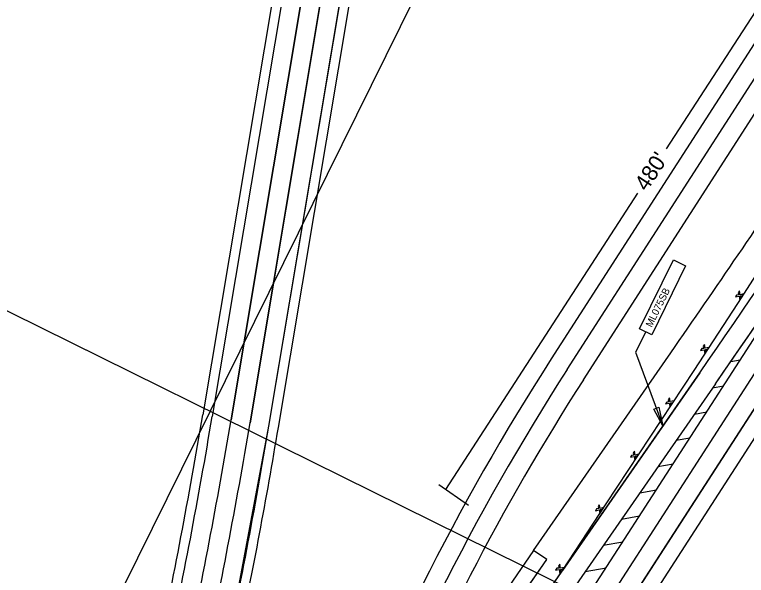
# Model space of a CAD drawing. Extents: x 14097936 to 14128734, y 8632000 to 8683104.
# Drawn here: x 14118895.5 to 14119353.7, y 8669041.8 to 8669393 of the extents above; entities that cross this region are included whole.
import ezdxf

# ---------------------------------------------------------------- set-up
doc = ezdxf.new("R2010")
doc.units = 0
for name, color, linetype in [('Cell', 7, 'Continuous'), ('dsn_stg_shd_prev', 7, 'Continuous'), ('dsnNonPlotable', 7, 'Continuous'), ('dsnPaintExistingChannelizingLaneWhite', 7, 'Continuous'), ('dsnPaintExistingDoubleCenterYellow', 7, 'Continuous'), ('dsnPaintExistingEdgeLineRightWhite', 7, 'Continuous'), ('dsnPaintExistingNoPassingYellow', 7, 'Continuous'), ('dsnPaintPlaceBrokenLaneWhite', 7, 'Continuous'), ('dsnPaintPlaceChannelizingLaneWhite', 7, 'Continuous'), ('dsnPaintPlaceChannelizingLaneYellow', 7, 'Continuous'), ('dsnPaintPlaceEdgeLineRightWhite', 7, 'Continuous'), ('dsnPavementRmvl', 7, 'Continuous'), ('dsnShadingPaved', 7, 'Continuous'), ('dsnStdLabel', 7, 'Continuous'), ('dsnStgShadingPropPav', 7, 'Continuous'), ('dsnTapePlaceChannelizingLaneWhite', 7, 'Continuous'), ('Text', 7, 'Continuous')]:
    doc.layers.add(name, color=color, linetype=linetype)

msp = doc.modelspace()

# ---------------------------------------------------------------- linework, layer by layer
at = {"layer": 'Cell'}
for p, q in [((14119347.58, 8669217.34), (14119346.82, 8669216.19)), ((14119349, 8669217.45), (14119347.58, 8669217.34)), ((14119349.29, 8669219.95), (14119348.54, 8669218.8)), ((14119348.54, 8669218.8), (14119349, 8669217.45)), ((14119349.78, 8669217.61), (14119349.29, 8669219.95)), ((14119352.12, 8669218.1), (14119349.78, 8669217.61)), ((14119349.94, 8669216.84), (14119351.36, 8669216.95)), ((14119350.4, 8669215.49), (14119349.94, 8669216.84)), ((14119351.36, 8669216.95), (14119352.12, 8669218.1)), ((14119346.82, 8669216.19), (14119349.16, 8669216.67)), ((14119349.16, 8669216.67), (14119349.64, 8669214.34)), ((14119349.64, 8669214.34), (14119350.4, 8669215.49)), ((14119327.42, 8669186.46), (14119326.66, 8669185.31)), ((14119326.66, 8669185.31), (14119327.12, 8669183.96)), ((14119327.9, 8669184.12), (14119327.42, 8669186.46)), ((14119325.7, 8669183.85), (14119324.95, 8669182.7)), ((14119324.95, 8669182.7), (14119327.29, 8669183.18)), ((14119327.12, 8669183.96), (14119325.7, 8669183.85)), ((14119327.29, 8669183.18), (14119327.77, 8669180.84)), ((14119327.77, 8669180.84), (14119328.52, 8669181.99)), ((14119330.24, 8669184.6), (14119327.9, 8669184.12)), ((14119328.06, 8669183.34), (14119329.49, 8669183.46)), ((14119328.52, 8669181.99), (14119328.06, 8669183.34)), ((14119329.49, 8669183.46), (14119330.24, 8669184.6)), ((14119305.52, 8669152.98), (14119304.77, 8669151.83)), ((14119306.01, 8669150.64), (14119305.52, 8669152.98)), ((14119303.81, 8669150.37), (14119303.05, 8669149.22)), ((14119303.05, 8669149.22), (14119305.39, 8669149.7)), ((14119305.23, 8669150.48), (14119303.81, 8669150.37)), ((14119304.77, 8669151.83), (14119305.23, 8669150.48)), ((14119305.39, 8669149.7), (14119305.87, 8669147.37)), ((14119305.87, 8669147.37), (14119306.63, 8669148.51)), ((14119308.34, 8669151.13), (14119306.01, 8669150.64)), ((14119306.17, 8669149.86), (14119307.59, 8669149.98)), ((14119306.63, 8669148.51), (14119306.17, 8669149.86)), ((14119307.59, 8669149.98), (14119308.34, 8669151.13)), ((14119281.83, 8669116.95), (14119281.07, 8669115.8)), ((14119281.07, 8669115.8), (14119283.41, 8669116.28)), ((14119283.25, 8669117.06), (14119281.83, 8669116.95)), ((14119283.54, 8669119.56), (14119282.79, 8669118.41)), ((14119282.79, 8669118.41), (14119283.25, 8669117.06)), ((14119283.41, 8669116.28), (14119283.89, 8669113.94)), ((14119284.03, 8669117.22), (14119283.54, 8669119.56)), ((14119286.36, 8669117.7), (14119284.03, 8669117.22)), ((14119284.19, 8669116.44), (14119285.61, 8669116.55)), ((14119284.65, 8669115.09), (14119284.19, 8669116.44)), ((14119285.61, 8669116.55), (14119286.36, 8669117.7)), ((14119283.89, 8669113.94), (14119284.65, 8669115.09)), ((14119261.58, 8669086.12), (14119260.82, 8669084.98)), ((14119260.82, 8669084.98), (14119261.28, 8669083.63)), ((14119262.06, 8669083.79), (14119261.58, 8669086.12)), ((14119264.4, 8669084.27), (14119262.06, 8669083.79)), ((14119263.64, 8669083.12), (14119264.4, 8669084.27)), ((14119259.86, 8669083.51), (14119259.11, 8669082.36)), ((14119259.11, 8669082.36), (14119261.44, 8669082.85)), ((14119261.28, 8669083.63), (14119259.86, 8669083.51)), ((14119261.44, 8669082.85), (14119261.93, 8669080.51)), ((14119261.93, 8669080.51), (14119262.68, 8669081.66)), ((14119262.22, 8669083.01), (14119263.64, 8669083.12)), ((14119262.68, 8669081.66), (14119262.22, 8669083.01)), ((14119236.9, 8669048.78), (14119236.06, 8669047.68)), ((14119236.06, 8669047.68), (14119236.43, 8669046.31)), ((14119237.21, 8669046.41), (14119236.9, 8669048.78)), ((14119235, 8669046.29), (14119234.17, 8669045.2)), ((14119234.17, 8669045.2), (14119236.53, 8669045.52)), ((14119236.43, 8669046.31), (14119235, 8669046.29)), ((14119236.53, 8669045.52), (14119236.85, 8669043.15)), ((14119236.85, 8669043.15), (14119237.69, 8669044.25)), ((14119239.58, 8669046.73), (14119237.21, 8669046.41)), ((14119237.32, 8669045.62), (14119238.75, 8669045.64)), ((14119237.69, 8669044.25), (14119237.32, 8669045.62)), ((14119238.75, 8669045.64), (14119239.58, 8669046.73))]:
    msp.add_line(p, q, dxfattribs=at)
at = {"layer": 'dsn_stg_shd_prev'}
for p, q in [((14119060.64, 8669134.39), (14119230.09, 8670146.06)), ((14119151.79, 8669969.11), (14119013.3, 8669142.32))]:
    msp.add_line(p, q, dxfattribs=at)
for radius, start in [(3476, 347.93292), (3524, 348.29238)]:
    msp.add_arc((14115585.06, 8669716.53), radius, start, 350.49147, dxfattribs=at)
at = {"layer": 'dsnNonPlotable'}
for points in [[(14119315.27, 8668607.09), (14120010, 8670012.23), (14119557.31, 8670236.05), (14118862.58, 8668830.91)], [(14118047.21, 8667875.87), (14118741.94, 8669281.01), (14119647.32, 8668833.36), (14118952.59, 8667428.23)]]:
    msp.add_lwpolyline(points, close=True, dxfattribs=at)
at = {"layer": 'dsnPaintExistingChannelizingLaneWhite'}
for p, q in [((14119434.72, 8669493.24), (14119231.48, 8669177.36)), ((14119251.66, 8669164.37), (14119454.9, 8669480.25))]:
    msp.add_line(p, q, dxfattribs=at)
for radius, end in [(1512, 159.62671), (1488, 158.15787)]:
    msp.add_arc((14120503.02, 8668359.24), radius, 147.24256, end, dxfattribs=at)
at = {"layer": 'dsnPaintExistingDoubleCenterYellow'}
msp.add_line((14119241.57, 8669170.86), (14119444.81, 8669486.75), dxfattribs=at)
msp.add_arc((14120503.02, 8668359.24), 1500, 147.24256, 159.62671, dxfattribs=at)
at = {"layer": 'dsnPaintExistingEdgeLineRightWhite'}
msp.add_line((14119184.51, 8670128.17), (14119019.22, 8669141.32), dxfattribs=at)
msp.add_line((14119184.51, 8670128.17), (14119019.22, 8669141.32), dxfattribs=at)
msp.add_lwpolyline([(14119029.87, 8669002.67), (14119054.72, 8669135.38), (14119224.18, 8670147.05)], dxfattribs=at)
msp.add_lwpolyline([(14119029.87, 8669002.67), (14119054.72, 8669135.38), (14119224.18, 8670147.05)], dxfattribs=at)
msp.add_arc((14115585.06, 8669716.53), 3482, 347.93292, 350.49147, dxfattribs=at)
msp.add_arc((14115585.06, 8669716.53), 3482, 347.93292, 350.49147, dxfattribs=at)
at = {"layer": 'dsnPaintExistingNoPassingYellow'}
for p, q in [((14119031.05, 8669139.34), (14119200.51, 8670151.01)), ((14119212.34, 8670149.03), (14119042.89, 8669137.36))]:
    msp.add_line(p, q, dxfattribs=at)
for radius in [3494, 3506]:
    msp.add_arc((14115585.06, 8669716.53), radius, 347.93292, 350.49147, dxfattribs=at)
at = {"layer": 'dsnPaintPlaceBrokenLaneWhite'}
msp.add_line((14119527.44, 8669429.79), (14119185.09, 8668899.43), dxfattribs=at)
at = {"layer": 'dsnPaintPlaceChannelizingLaneWhite'}
msp.add_line((14119213.91, 8669009.38), (14119238.52, 8669044.85), dxfattribs=at)
at = {"layer": 'dsnPaintPlaceChannelizingLaneYellow'}
for p, q in [((14119175.01, 8668905.94), (14119397.41, 8669250.48)), ((14119343.89, 8669175.72), (14119349.86, 8669176.81)), ((14119334.31, 8669161.88), (14119223.77, 8669002.54)), ((14119332.51, 8669159.28), (14119339.34, 8669160.51)), ((14119321.11, 8669142.84), (14119328.83, 8669144.24)), ((14119309.71, 8669126.41), (14119318.33, 8669127.97)), ((14119298.31, 8669109.98), (14119307.83, 8669111.7)), ((14119286.91, 8669093.55), (14119297.32, 8669095.43)), ((14119275.51, 8669077.11), (14119286.82, 8669079.16)), ((14119264.11, 8669060.68), (14119276.32, 8669062.89)), ((14119252.71, 8669044.25), (14119265.82, 8669046.62))]:
    msp.add_line(p, q, dxfattribs=at)
msp.add_arc((14111644.26, 8674494.18), 9357.9, 325.262476, 326.828528, dxfattribs=at)
at = {"layer": 'dsnPaintPlaceEdgeLineRightWhite'}
msp.add_line((14119195.17, 8668892.92), (14119537.53, 8669423.29), dxfattribs=at)
at = {"layer": 'dsnPavementRmvl'}
for p, q in [((14119434.72, 8669493.24), (14119231.48, 8669177.36)), ((14119251.66, 8669164.37), (14119454.9, 8669480.25))]:
    msp.add_line(p, q, dxfattribs=at)
for radius, end in [(1512, 159.62671), (1488, 158.15787)]:
    msp.add_arc((14120503.02, 8668359.24), radius, 147.24256, end, dxfattribs=at)
at = {"layer": 'dsnShadingPaved'}
for p, q in [((14119188.67, 8670153), (14119019.22, 8669141.32)), ((14119200.51, 8670151.01), (14119031.05, 8669139.34)), ((14119031.05, 8669139.34), (14119200.51, 8670151.01)), ((14119212.34, 8670149.03), (14119042.89, 8669137.36)), ((14119042.89, 8669137.36), (14119212.34, 8670149.03)), ((14119054.72, 8669135.38), (14119224.18, 8670147.05)), ((14119175.01, 8668905.94), (14119517.35, 8669436.29)), ((14119213.91, 8669009.38), (14119324.45, 8669168.72)), ((14119324.45, 8669168.72), (14119238.52, 8669044.85)), ((14119334.31, 8669161.88), (14119223.77, 8669002.54))]:
    msp.add_line(p, q, dxfattribs=at)
for points in [[(14119238.52, 8669044.85), (14119265.99, 8669086.65), (14119293.47, 8669128.44), (14119320.94, 8669170.24), (14119348.3, 8669212.11), (14119375.45, 8669254.16), (14119402.36, 8669296.35), (14119429.03, 8669338.69), (14119455.46, 8669381.17), (14119481.65, 8669423.79), (14119497.35, 8669449.49)], [(14119537.53, 8669423.29), (14119537.53, 8669423.29), (14119195.17, 8668892.92)]]:
    msp.add_lwpolyline(points, dxfattribs=at)
for centre, radius, start, end in [((14111929.66, 8674298.73), 9000, 325.249705, 327.157368), ((14111929.66, 8674298.73), 9000, 325.249705, 327.157368), ((14111929.66, 8674298.73), 9012, 325.249705, 327.157368), ((14115585.06, 8669716.53), 3482, 347.93292, 350.49147), ((14115585.06, 8669716.53), 3494, 347.93292, 350.49147), ((14115585.06, 8669716.53), 3494, 347.93292, 350.49147), ((14115585.06, 8669716.53), 3506, 347.93292, 350.49147), ((14115585.06, 8669716.53), 3506, 347.93292, 350.49147), ((14115585.06, 8669716.53), 3518, 347.93292, 350.49147)]:
    msp.add_arc(centre, radius, start, end, dxfattribs=at)
at = {"layer": 'dsnStdLabel'}
for p, q in [((14119425.08, 8669496.82), (14119303.44, 8669308.96)), ((14119285.45, 8669281.18), (14119165.31, 8669095.64)), ((14119179.69, 8669085.67), (14119161.2, 8669098.49))]:
    msp.add_line(p, q, dxfattribs=at)
at = {"layer": 'dsnStgShadingPropPav'}
for p, q in [((14119060.64, 8669134.39), (14119230.09, 8670146.06)), ((14119151.79, 8669969.11), (14119013.3, 8669142.32)), ((14119434.72, 8669493.24), (14119231.48, 8669177.36)), ((14119251.66, 8669164.37), (14119454.9, 8669480.25)), ((14119220.45, 8669057.39), (14119195.84, 8669021.92)), ((14119228.66, 8669051.69), (14119220.45, 8669057.39)), ((14119204.06, 8669016.22), (14119228.66, 8669051.69))]:
    msp.add_line(p, q, dxfattribs=at)
for points in [[(14119420.33, 8669223.29), (14119201.18, 8668883.8), (14119172.86, 8668902.61), (14119172.76, 8668902.45), (14119141.1, 8668923.47)], [(14119204.06, 8669016.22), (14119228.66, 8669051.69), (14119220.45, 8669057.39), (14119306.38, 8669181.26)]]:
    msp.add_lwpolyline(points, dxfattribs=at)
for centre, radius, start, end in [((14111929.66, 8674298.73), 8978, 325.249705, 326.199346), ((14120503.02, 8668359.24), 1512, 147.24256, 159.62671), ((14120503.02, 8668359.24), 1488, 147.24256, 158.15787), ((14115585.06, 8669716.53), 3476, 347.93292, 350.49147), ((14115585.06, 8669716.53), 3524, 348.29238, 350.49147)]:
    msp.add_arc(centre, radius, start, end, dxfattribs=at)
at = {"layer": 'dsnTapePlaceChannelizingLaneWhite'}
msp.add_lwpolyline([(14119238.52, 8669044.85), (14119265.99, 8669086.65), (14119293.47, 8669128.44), (14119320.94, 8669170.24), (14119348.3, 8669212.11), (14119375.45, 8669254.16), (14119402.36, 8669296.35), (14119429.03, 8669338.69), (14119455.46, 8669381.17), (14119481.65, 8669423.79), (14119497.35, 8669449.49)], dxfattribs=at)
at = {"layer": 'Text'}
for points in [[(14119286.86, 8669196.28), (14119308.12, 8669239.44), (14119315.66, 8669235.73), (14119294.4, 8669192.57)], [(14119286.86, 8669196.28), (14119308.12, 8669239.44), (14119315.66, 8669235.73), (14119294.4, 8669192.57)], [(14119301.43, 8669135.54), (14119295.65, 8669145.99), (14119298.97, 8669147.23)]]:
    msp.add_lwpolyline(points, close=True, dxfattribs=at)
msp.add_lwpolyline([(14119290.63, 8669194.43), (14119284.23, 8669181.63), (14119301.43, 8669135.54)], dxfattribs=at)

# ---------------------------------------------------------------- texts
at = {"layer": 'dsnStdLabel'}
msp.add_text("480'", height=10, rotation=56.6002, dxfattribs=at).set_placement((14119291.29, 8669281.79))
at = {"layer": 'Text'}
msp.add_text('ML075SB', height=4.484, rotation=63.7805, dxfattribs=at).set_placement((14119294.38, 8669196.81))

doc.saveas('drawing.dxf')
